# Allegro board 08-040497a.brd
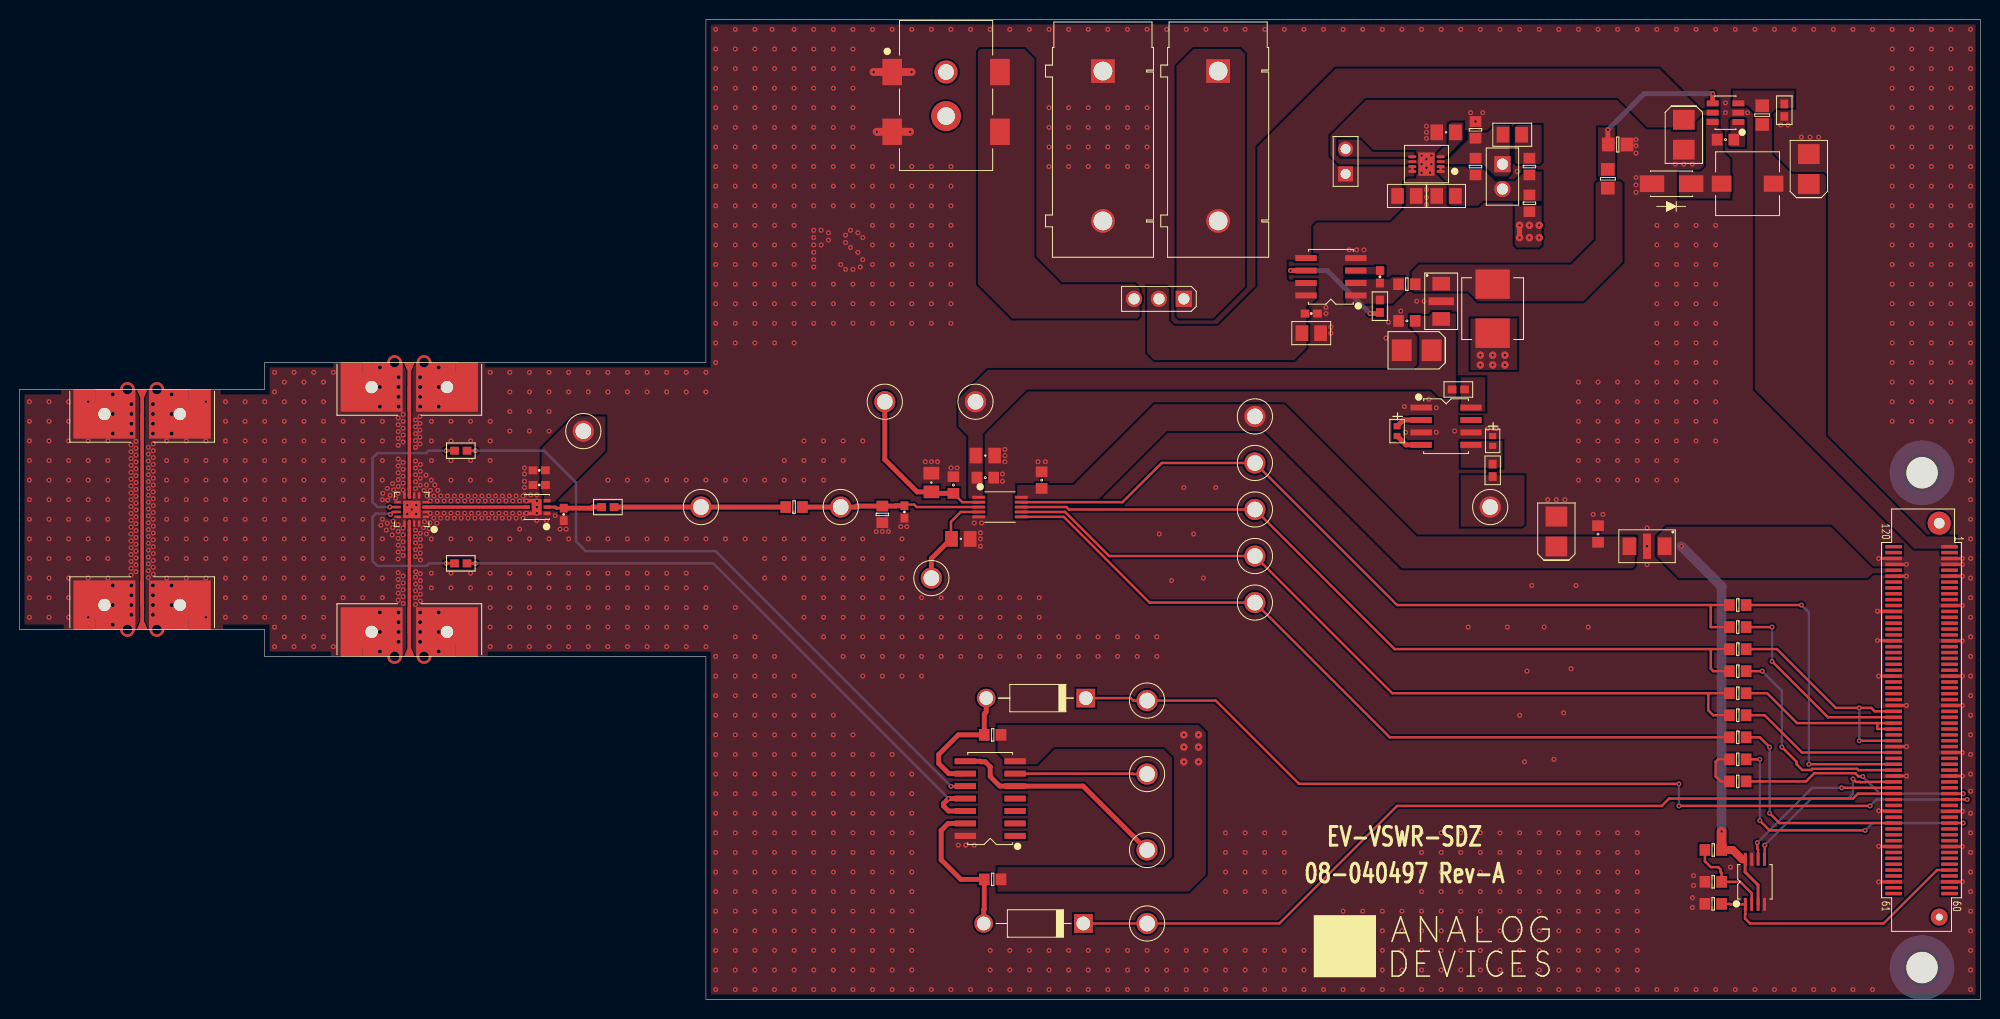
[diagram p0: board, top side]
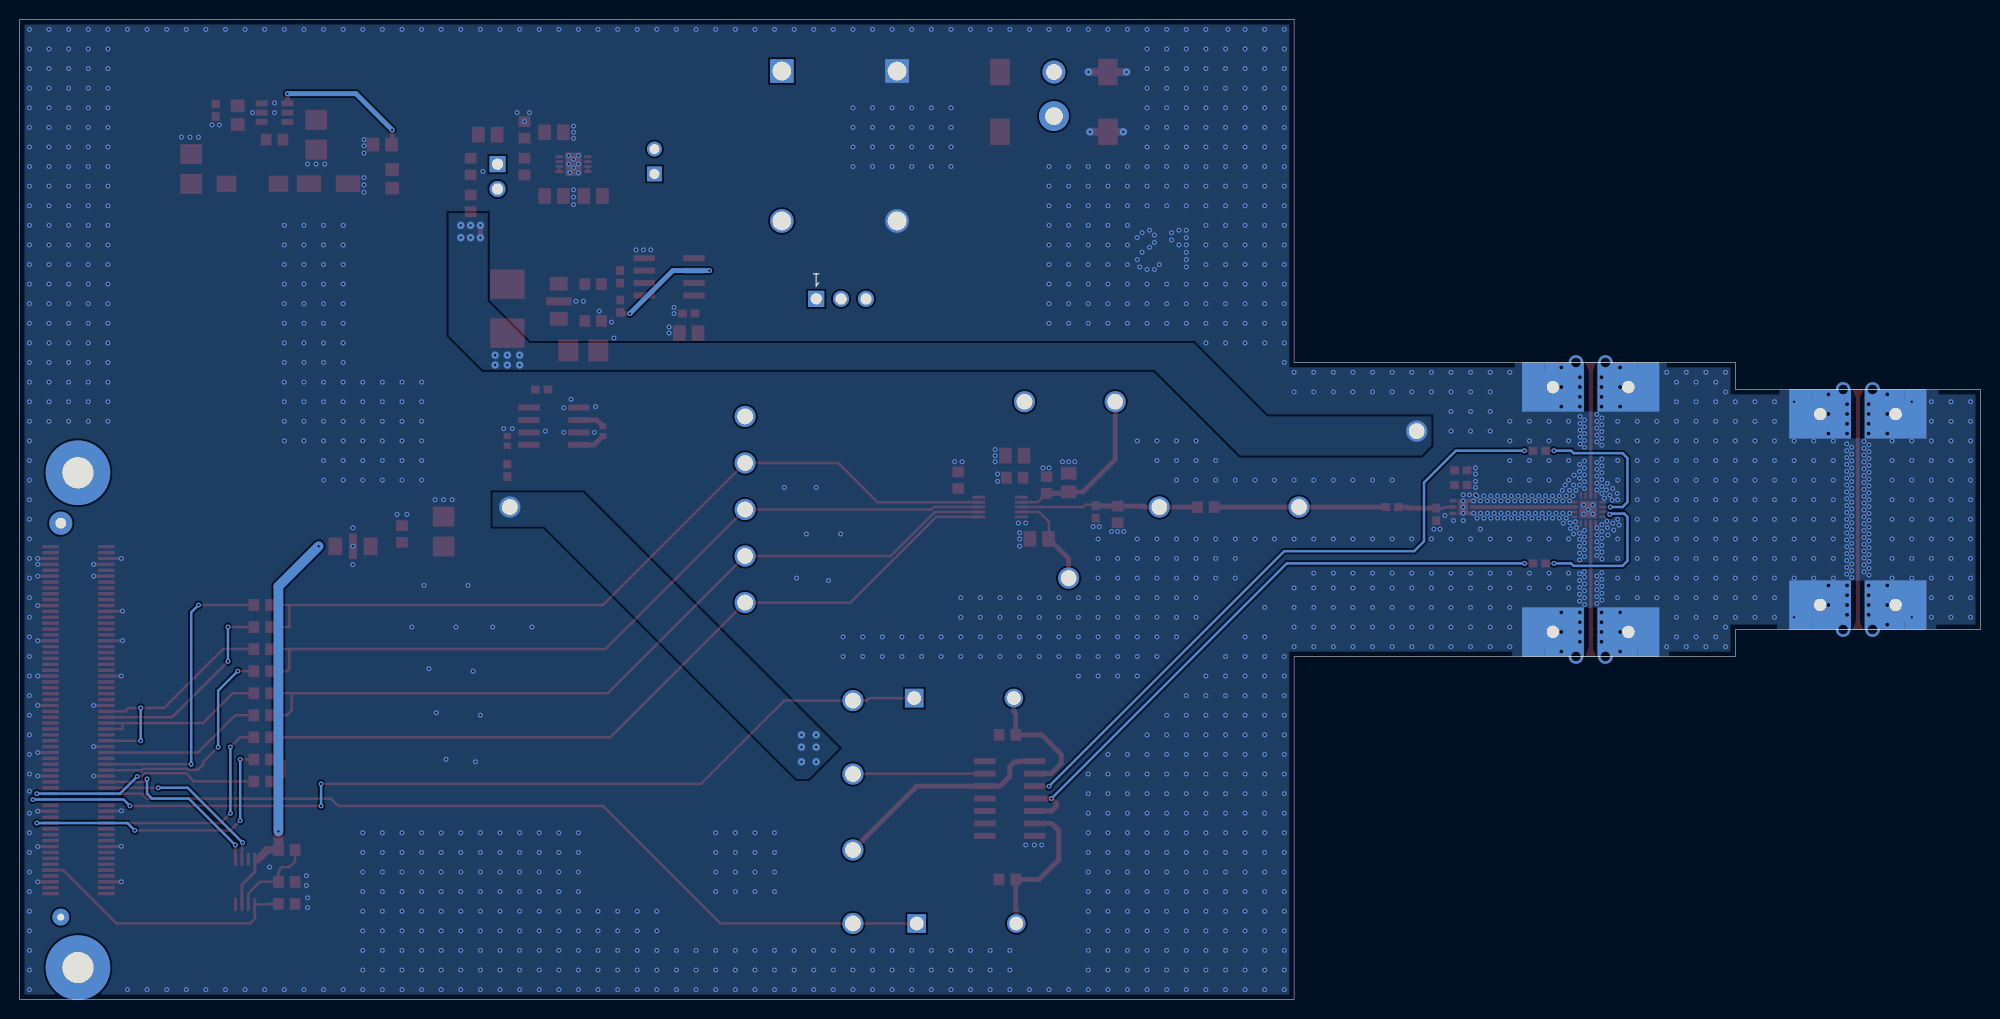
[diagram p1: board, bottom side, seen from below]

Outline 200 x 100 mm; copper layers: TOP, L2-GND, L3-GND, BOTTOM. Coordinates in mm from the lower left corner of the outline.
Outline path: 0,62.25 0,37.75 25,37.75 25,35 70,35 70,0 200,0 200,100 70,100 70,65 25,65 25,62.25 0,62.25

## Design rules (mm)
nets with their own width: min track width 0.3; nets AGND

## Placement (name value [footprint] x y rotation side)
A  WHT  [CNLOOPTP]  115 15.25 0 top
B  WHT  [CNLOOPTP]  115 23 0 top
C1  100pF  [C0402]  53 54 180 top
C2  0.1UF  [C0402]  53 52.5 180 top
C3  TBD0402  [C0402]  55.5 49.5 270 top
C9  1uF  [C0805]  98.5 55.5 0 top
C10  0.1uF  [C0603]  98.5 53.25 0 top
C11  0.1uF  [C0603]  95.25 52.5 90 top
C12  1uF  [C0805]  93 52.75 90 top
C14  1uF  [C0805]  96 47 0 top
C15  0.1uF  [C0603]  104.25 53 90 top
C17  0.01uF  [C0402]  131.75 70 0 top
C18  0.01UF  [C0402]  138.75 73.75 270 top
C19  0.1uF  [C0603]  141.5 69.25 180 top
C20  10uF  [C3528]  142.5 66.25 180 top
C21  10uF  [C3528]  169.75 88.25 270 top
C22  0.1uF  [C0603]  174 87.75 180 top
C23  10uF  [C3528]  182.5 84.75 90 top
C24  0.1uF  [C0603]  161 47.5 90 top
C25  10uF  [C3528]  156.75 47.75 90 top
C26  1UF  [C0805H53]  131.75 68 0 top
C29  1UF  [C0805H53]  152.25 88.25 0 top
C30  4.7UF  [C0805H53]  145.5 82 0 top
C31  1000pF  [C0805]  145.5 88.5 0 top
C32  4.7UF  [C0805H53]  141.5 82 180 top
C35  10uF  [CPL0402]  150.25 57 270 top
C36  10uF  [CPL0402]  140.5 58 270 top
C37  TBD0402  [C0402]  90.25 49.75 270 top
D1  B230A-13-F  [SMA-2]  168.5 83.25 180 top
D2  1N4733A  [DO41]  108.5 7.75 180 top
D3  1N4733A  [DO41]  108.75 30.75 180 top
GND  571-0100  [CNDELTRON-571]  110.5 94.75 270 top
GPIO1  WHT  [CNLOOPTP]  115 7.75 0 top
GPIO2  WHT  [CNLOOPTP]  115 30.5 0 top
J3  02K243-40M  [CNROS02K243-40M]  12.5 37.75 270 top
J4  FX8-120S-SV(21)  [CNHRSFX8-120S-SV_A]  194 28.5 270 top
J5  02K243-40M  [CNROS02K243-40M]  12.5 62.25 90 top
L1  6.8uH  [LSMSQ236H79_B]  176.25 83.25 0 top
L2  33uH  [L2525]  150.25 70.5 90 top
LC1  1000pF  [FLSML126W71H87]  145 71.25 270 top
LC2  1000pF  [FLSML126W71H87]  166 46.25 180 top
LK6  SAMTECTSW10608GS3PIN  [CNBERG1X3H205LD36]  118.75 71.5 180 top
LK21  M20-9990245  [CNHARWIN-M20-9990246]  151.25 85.25 270 top
LK22  69157-102  [CNBERG69157-102]  135.25 84.25 90 top
NOREF  -  []  261.5 -98 0 top
NOREF#2  -  []  40.54 48.23 0 top
NOREF#3  -  []  70 0 90 top
NOREF#4  -  []  39.11 52.78 0 top
NOREF#5  -  []  -153.6 -177.4 0 top
NOREF#6  -  []  200 0 90 top
NOREF#7  -  []  40.89 52.79 0 top
NOREF#8  -  []  0 62.25 0 top
NOREF#9  -  []  0 37.75 90 top
NOREF#10  -  []  -153.6 -177.4 0 top
NOREF#11  -  []  25 65 0 top
NOREF#12  -  []  70 65 90 top
NOREF#13  -  []  44.08 49.26 0 top
NOREF#14  -  []  -133.3 -28.65 0 top
NOREF#15  -  []  70 100 0 top
NOREF#16  -  []  25 62.25 90 top
NOREF#17  -  []  25 35 90 top
NOREF#18  -  []  38.12 33.5 0 top
NOREF#19  -  []  41.3 51.3 0 top
NOREF#20  -  []  -153.6 -177.4 0 top
NOREF#21  -  []  245.81 331.87 0 top
NOREF#22  -  []  129.5 140.25 0 top
NOREF#23  -  []  44.07 50.74 0 top
NOREF#24  -  []  132 2.25 180 bottom
R1  0  [R0402]  60 50.25 0 top
R12  330K  [R0402]  138.75 70.75 90 top
R13  3K  [R0805]  162 83.75 90 top
R14  1.5K  [R0805]  163 87.25 0 top
R15  53.6K  [R0805]  177.75 90.25 90 top
R16  10.2K  [R0402]  180 90.75 270 top
R17  TBD0603  [R0603]  175.25 33.5 180 top
R18  TBD0603  [R0603]  175.25 40.25 180 top
R19  TBD0603  [R0603]  175.25 29 180 top
R20  0  [R0603]  175.25 35.75 180 top
R21  0  [R0603]  175.25 31.25 180 top
R22  0  [R0603]  175.25 38 180 top
R23  0  [R0603]  175.25 24.5 0 top
R24  TBD0603  [R0603]  175.25 22.25 0 top
R25  TBD0603  [R0603]  175.25 26.75 180 top
R26  TBD0603  [R0603]  172.75 15.25 180 top
R27  100K  [R0603]  172.75 12 180 top
R28  100K  [R0603]  172.75 9.75 180 top
R30  10K  [R0603]  99.25 12.25 0 top
R31  200  [R0603]  79 50.25 0 top
R32  0  [R0603]  154 81.25 270 top
R33  3K  [R0603]  154 85 270 top
R34  120K  [R0603]  148.5 85 270 top
R35  39K  [R0603]  148.5 88.75 270 top
R36  10K  [R0603]  99.25 27 0 top
R37  0  [R0402]  146.75 62.25 180 top
R38  0  [R0402]  150.25 54 270 top
R39  0  [R0603]  141.5 73 0 top
R40  340  [R0603]  88 49.5 270 top
R41  100  [R0402]  45 44.5 180 top
R42  100  [R0402]  45 56 180 top
RF1  02K243-40M  [CNROS02K243-40M]  39.75 65 90 top
RF2  02K243-40M  [CNROS02K243-40M]  39.75 35 270 top
T1  WHT  [CNLOOPTP]  97.5 61 0 top
T2  WHT  [CNLOOPTP]  88.25 61 0 top
T3  WHT  [CNLOOPTP]  83.75 50.25 0 top
T4  WHT  [CNLOOPTP]  93 43 0 top
T6  WHT  [CNLOOPTP]  126 40.5 0 top
T7  WHT  [CNLOOPTP]  126 45.25 0 top
T8  WHT  [CNLOOPTP]  126 50 0 top
T9  WHT  [CNLOOPTP]  126 54.75 0 top
T10  WHT  [CNLOOPTP]  126 59.5 0 top
U1  ADL6010ACPZN  [UQFN6_2_05X2_05_PAD1_6X1_A]  52.75 50.25 90 top
U2  AD7091RBRMZ  [RM10]  100 50.25 270 top
U5  24LC32A-I/MS  [MSOP8]  177 12 0 top
U6  ADP3303ARZ-5  [SO8]  133.75 73.75 90 top
U7  ADP2301AUJZ  [TSOT23_6]  174 90.5 90 top
U8  ADM7170ACPZ  [DFN8_3X3_PAD2_38X1_64]  143.5 85.25 90 top
U9  74LV04AD  [SO14]  99 20.5 90 top
U10  -  [HMC547LP3E]  40 50 90 top
U11  ADM660ARZ  [SO8]  145.5 58.5 270 top
V_OUT  WHT  [CNLOOPTP]  69.5 50.25 0 top
VDET  RED  [CNLOOPTP]  57.5 58 0 top
VNEG  WHT  [CNLOOPTP]  150 50.25 0 top
VSUPPLY  KLDX-SMT2-0202-ATR  [CNKYCONKLDX-SMT2-0202]  94.5 92.25 270 top
VSUPPLY_ALT  571-0500  [CNDELTRON-571]  122.25 94.75 270 top

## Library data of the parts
A B GPIO1 GPIO2 T1-T4 T6-T10 V_OUT VNEG = CNTP1P: User Part Number: UPN; alternate symbols: (CNBANANA_ALT); part number: CNTP1P_TH-WHT,E000946,CNLOOPTP
C1 = CAP: Tolerance: 5; User Part Number: UPN; part number: CAP_SM-100PF,50V,5,E007896,C0402; tolerance: 5
C2 = CAP: Tolerance: 10; User Part Number: UPN; part number: CAP_SM-0.1UF,16V,10,E007200,C0402; tolerance: 10
C3 C37 = CAP: User Part Number: UPN; part number: CAP_SM-TBD0402,TBD0402,TBD0402,E000381,C0402
C9 C12 C14 = CAP: Tolerance: 10; User Part Number: UPN; part number: CAP_SM-1UF,100V,10,E014208,C0805; tolerance: 10
C10 C11 = CAP: Tolerance: 10; User Part Number: UPN; part number: CAP_SM-0.1UF,50V,10,E011865,C0603; tolerance: 10
C15 C19 C22 C24 = CAP: Tolerance: 10; User Part Number: UPN; part number: CAP_SM-0.1UF,50V,10,E015248,C0603; tolerance: 10
C17 = CAP: Tolerance: -0.25; User Part Number: UPN; part number: CAP_SM-0.01UF,50V,-0.25,E012614,C0402; tolerance: -0.25
C18 = CAP: Tolerance: 10; User Part Number: UPN; part number: CAP_SM-0.01UF,25V,10,E010983,C0402; tolerance: 10
C20 C21 C23 C25 = CAPP: User Part Number: UPN; Tolerance: 10; part number: CAPP_SM-10UF,20V,10,E011346,C3528; tolerance: 10
C26 C29 = CAP: Tolerance: 10; User Part Number: UPN; part number: CAP_SM-1UF,50V,10,E007202,C0805H53; tolerance: 10
C30 C32 = CAP: Tolerance: 10; User Part Number: UPN; part number: CAP_SM-4.7UF,25V,10,E006908,C0805H53; tolerance: 10
C31 = CAP: Tolerance: 5; User Part Number: UPN; part number: CAP_SM-1000PF,50V,5,E010100,C0805; tolerance: 5
C35 C36 = CAPP: User Part Number: UPN; Tolerance: 20; part number: CAPP_SM-10UF,6.3V,20,E022099,CPL0402; tolerance: 20
D1 = DIOSCHOTTKY: User Part Number: UPN; Tolerance: N/A; alternate symbols: (SOD882L_ALT); part number: DIOSCHOTTKY_SM-B230A-13-F,30V,N/A,E012952,SMA-2; tolerance: N/A
D2 D3 = DIOZNR: Tolerance: 5; User Part Number: UPN; part number: DIOZNR_TH-1N4733A,5.1V,5,E001229,DO41; tolerance: 5
GND = CN2P: User Part Number: UPN; part number: CN2P_TH-571-0100,E007691,CNDELTRON-571
J3 J5 RF1 RF2 = CNBNC3P: User Part Number: UPN; alternate symbols: (CNROS32K243-40ML5_ALT); part number: CNBNC3P_SM-02K243-40M,E010821,CNROS02K243-40M
J4 = CN120P_V4: User Part Number: UPN; part number: CN120P_V4_SM-FX8-120S-SV(21),E016993,CNHRSFX8-120S-SV_A
L1 = IND: Tolerance: 30; User Part Number: UPN; alternate symbols: (L0402-2,L0603_ALT,L1008L_ALT); part number: IND_SM-6.8UH,30,E021189,LSMSQ236H79_B; tolerance: 30
L2 = IND: Tolerance: 20; User Part Number: UPN; alternate symbols: (L0402-2,L0603_ALT,L1008L_ALT); part number: IND_SM-33UH,20,E002425,L2525; tolerance: 20
LC1 LC2 = FLTR3P_V3: User Part Number: UPN; part number: FLTR3P_V3_SM-1000PF,E019686,FLSML126W71H87
LK6 = CN3P: User Part Number: UPN; part number: CN3P_TH-SAMTECTSW10608GS3PIN,E000812,CNBERG1X3H205LD36
LK21 = CNJMPRSHRT: User Part Number: UPN; part number: CNJMPRSHRT_TH-M20-9990245,E019487,CNHARWIN-M20-9990246
LK22 = CNJMPRSHRT: User Part Number: UPN; part number: CNJMPRSHRT_TH-69157-102,E000942,CNBERG69157-102
R1 R37 R38 = RES: Tolerance: 5; User Part Number: UPN; part number: RES_SM-0,E003438,1/16W,5,R0402; tolerance: 5
R12 = RES: Tolerance: 5; User Part Number: UPN; part number: RES_SM-330K,E003461,1/16W,5,R0402; tolerance: 5
R13 = RES: Tolerance: 0.1; User Part Number: UPN; part number: RES_SM-3K,E013665,1/4W,0.1,R0805; tolerance: 0.1
R14 = RES: Tolerance: 0.1; User Part Number: UPN; part number: RES_SM-1.5K,E003822,1/10W,0.1,R0805; tolerance: 0.1
R15 = RES: Tolerance: 1; User Part Number: UPN; part number: RES_SM-53.6K,E003980,1/8W,1,R0805; tolerance: 1
R16 = RES: Tolerance: 1; User Part Number: UPN; part number: RES_SM-10.2K,E019451,1/16W,1,R0402; tolerance: 1
R17-R19 R24-R26 = RES: User Part Number: UPN; part number: RES_SM-TBD0603,E004050,TBD0603,TBD0603,R0603
R20-R23 R32 R39 = RES: Tolerance: 1; User Part Number: UPN; part number: RES_SM-0,E004207,1/16W,1,R0603; tolerance: 1
R27 R28 = RES: Tolerance: 1; User Part Number: UPN; part number: RES_SM-100K,E018430,1/16W,1,R0603; tolerance: 1
R30 R36 = RES: Tolerance: 0.1; User Part Number: UPN; part number: RES_SM-10K,E003965,1/10W,0.1,R0603; tolerance: 0.1
R31 = RES: Tolerance: 0.1; User Part Number: UPN; part number: RES_SM-200,E003955,1/10W,0.1,R0603; tolerance: 0.1
R33 = RES: Tolerance: 5; User Part Number: UPN; part number: RES_SM-3K,E003850,1/10W,5,R0603; tolerance: 5
R34 = RES: Tolerance: 1; User Part Number: UPN; part number: RES_SM-120K,E007774,0.1W,1,R0603; tolerance: 1
R35 = RES: Tolerance: 1; User Part Number: UPN; part number: RES_SM-39K,E004234,1/16W,1,R0603; tolerance: 1
R40 = RES: Tolerance: 1; User Part Number: UPN; part number: RES_SM-340,E012541,1/10W,1,R0603; tolerance: 1
R41 R42 = RES: Tolerance: 1; User Part Number: UPN; part number: RES_SM-100,E003760,1/16W,1,R0402; tolerance: 1
U1 = ADL6010: User Part Number: UPN; alternate symbols: (UQFN6_2_05X2_05_PAD1_6X1); part number: ADL6010_SM-ADL6010ACPZN,E019839,UQFN6_2_05X2_05_PAD1_6X1_A
U2 = AD7091R_V2: User Part Number: UPN; part number: AD7091R_V2_SM-AD7091RBRMZ,E015495,RM10
U5 = IC24FC256: User Part Number: UPN; part number: IC24FC256_SM-24LC32A-I/MS,E014160,MSOP8
U6 = ADP3303: User Part Number: UPN; part number: ADP3303_SM-ADP3303ARZ-5,E004966,SO8
U7 = ADP2301: User Part Number: UPN; part number: ADP2301_SM-ADP2301AUJZ,E007310,TSOT23_6
U8 = ADM7170: User Part Number: UPN; part number: ADM7170_SM-ADM7170ACPZ,E020662,DFN8_3X3_PAD2_38X1_64
U9 = 7404: User Part Number: UPN; part number: 7404_SM-74LV04AD,E002109,SO14
U10 = ICHMC547LP3E: User Part Number: UPN; part number: ICHMC547LP3E_SM-HMC547LP3E,E011702,HMC547LP3E
U11 = ADM660: User Part Number: UPN; part number: ADM660_TH-ADM660ARZ,E006022,SO8
VDET = CNTP1P: User Part Number: UPN; alternate symbols: (CNBANANA_ALT); part number: CNTP1P_TH-RED,E000947,CNLOOPTP
VSUPPLY = CN4P_V2: User Part Number: UPN; part number: CN4P_V2_SM-KLDX-SMT2-0202-ATR,E015303,CNKYCONKLDX-SMT2-0202
VSUPPLY_ALT = CN2P: User Part Number: UPN; part number: CN2P_TH-571-0500,E007692,CNDELTRON-571

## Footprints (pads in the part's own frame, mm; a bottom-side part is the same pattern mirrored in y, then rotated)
C0402
  rect 0.889x0.813 smd: 1(-0.635,0) 2(0.635,0)
C0603
  rect 1.092x1.194 smd: 1(-0.851,0) 2(0.851,0)
C0805
  rect 1.295x1.6 smd: 1(-0.953,0) 2(0.953,0)
C0805H53
  rect 1.295x1.6 smd: 1(-0.953,0) 2(0.953,0)
C3528
  rect 2.032x2.21 smd: N(1.524,0) P(-1.524,0)
CNBERG1X3H205LD36
  rect 1.651x1.651 hole 1.143: 1(0,0)
  round 1.651 hole 1.143: 2(2.54,0) 3(5.08,0)
CNBERG69157-102
  rect 1.524x1.524 hole 1.016: 1(0,0)
  round 1.524 hole 1.016: 2(2.54,0)
CNDELTRON-571
  rect 2.413x2.413 hole 1.905: 1(0,0)
  round 2.413 hole 1.905: 2(15.3,0)
CNHARWIN-M20-9990246
  rect 1.651x1.651 hole 1.143: 1(0,0)
  round 1.651 hole 1.143: 2(2.54,0)
CNHRSFX8-120S-SV_A
  round 3.302 hole 3.175 unplated: (-25.25,0.05) (25.25,0.05)
  round 2.362 hole 1.092 unplated: (-20.1,1.8)
  round 1.727 hole 0.711 unplated: (20.1,1.8)
  rect 0.356x1.702 smd: 1(-17.7,2.851) 2(-17.1,2.851) 3(-16.5,2.851) 4(-15.9,2.851) 5(-15.3,2.851) 6(-14.7,2.851) 7(-14.1,2.851) 8(-13.5,2.851) 9(-12.9,2.851) 10(-12.3,2.851) 11(-11.7,2.851) 12(-11.1,2.851) 13(-10.5,2.851) 14(-9.9,2.851) 15(-9.3,2.851) 16(-8.7,2.851) 17(-8.1,2.851) 18(-7.5,2.851) 19(-6.9,2.851) 20(-6.3,2.851) 21(-5.7,2.851) 22(-5.1,2.851) 23(-4.5,2.851) 24(-3.9,2.851) 25(-3.3,2.851) 26(-2.7,2.851) 27(-2.1,2.851) 28(-1.5,2.851) 29(-0.9,2.851) 30(-0.3,2.851) 31(0.3,2.851) 32(0.9,2.851) 33(1.5,2.851) 34(2.1,2.851) 35(2.7,2.851) 36(3.3,2.851) 37(3.9,2.851) 38(4.5,2.851) 39(5.1,2.851) 40(5.7,2.851) 41(6.3,2.851) 42(6.9,2.851) 43(7.5,2.851) 44(8.1,2.851) 45(8.7,2.851) 46(9.3,2.851) 47(9.9,2.851) 48(10.5,2.851) 49(11.1,2.851) 50(11.7,2.851) 51(12.3,2.851) 52(12.9,2.851) 53(13.5,2.851) 54(14.1,2.851) 55(14.7,2.851) 56(15.3,2.851) 57(15.9,2.851) 58(16.5,2.851) 59(17.1,2.851) 60(17.7,2.851) 61(17.7,-2.851) 62(17.1,-2.851) 63(16.5,-2.851) 64(15.9,-2.851) 65(15.3,-2.851) 66(14.7,-2.851) 67(14.1,-2.851) 68(13.5,-2.851) 69(12.9,-2.851) 70(12.3,-2.851) 71(11.7,-2.851) 72(11.1,-2.851) 73(10.5,-2.851) 74(9.9,-2.851) 75(9.3,-2.851) 76(8.7,-2.851) 77(8.1,-2.851) 78(7.5,-2.851) 79(6.9,-2.851) 80(6.3,-2.851) 81(5.7,-2.851) 82(5.1,-2.851) 83(4.5,-2.851) 84(3.9,-2.851) 85(3.3,-2.851) 86(2.7,-2.851) 87(2.1,-2.851) 88(1.5,-2.851) 89(0.9,-2.851) 90(0.3,-2.851) 91(-0.3,-2.851) 92(-0.9,-2.851) 93(-1.5,-2.851) 94(-2.1,-2.851) 95(-2.7,-2.851) 96(-3.3,-2.851) 97(-3.9,-2.851) 98(-4.5,-2.851) 99(-5.1,-2.851) 100(-5.7,-2.851) 101(-6.3,-2.851) 102(-6.9,-2.851) 103(-7.5,-2.851) 104(-8.1,-2.851) 105(-8.7,-2.851) 106(-9.3,-2.851) 107(-9.9,-2.851) 108(-10.5,-2.851) 109(-11.1,-2.851) 110(-11.7,-2.851) 111(-12.3,-2.851) 112(-12.9,-2.851) 113(-13.5,-2.851) 114(-14.1,-2.851) 115(-14.7,-2.851) 116(-15.3,-2.851) 117(-15.9,-2.851) 118(-16.5,-2.851) 119(-17.1,-2.851) 120(-17.7,-2.851)
CNKYCONKLDX-SMT2-0202
  round 2.362 hole 1.6 unplated: (-2.4,0)
  round 3.048 hole 1.803 unplated: (2.1,0)
  rect 2.692x2.007 smd: 1(-2.4,-5.497) 2(3.7,-5.497) 3(3.7,5.497) 4(-2.4,5.497)
CNLOOPTP
  round 2.159 hole 1.6: 1(0,0)
CNROS02K243-40M
  custom 0.275x0.275 smd: 1(-2.5,0)
  custom 1.251x1.251 hole 2.108: 2(-2.508,3.848) 3(-2.508,-3.848)
CPL0402
  rect 0.635x0.711 smd: N(0.5,0) P(-0.5,0)
DFN8_3X3_PAD2_38X1_64
  oval 0.305x0.838 smd: 1(-0.75,-1.45) 2(-0.25,-1.45) 3(0.25,-1.45) 4(0.75,-1.45) 5(0.75,1.45) 6(0.25,1.45) 7(-0.25,1.45) 8(-0.75,1.45)
  rect 2.388x1.651 smd: PAD(0,0)
DO41
  round 1.905 hole 1.397: A(10.16,0)
  rect 1.905x1.905 hole 1.397: C(0,0)
FLSML126W71H87
  rect 1.397x1.803 smd: 1(-1.799,0) 3(1.799,0)
  rect 0.813x2.591 smd: 2(0,0)
HMC547LP3E
  rect 0.254x0.66 smd: 1(-0.751,-1.435) 2(-0.25,-1.435) 3(0.25,-1.435) 4(0.751,-1.435) 9(0.751,1.435) 10(0.25,1.435) 11(-0.25,1.435) 12(-0.751,1.435)
  rect 0.66x0.254 smd: 5(1.435,-0.751) 6(1.435,-0.25) 7(1.435,0.25) 8(1.435,0.751) 13(-1.435,0.751) 14(-1.435,0.25) 15(-1.435,-0.25) 16(-1.435,-0.751)
  rect 1.778x1.778 smd: PAD(0,0)
L2525
  rect 2.997x3.505 smd: 1(-2.502,0) 2(2.502,0)
LSMSQ236H79_B
  rect 2.007x1.651 smd: 1(-2.65,0) 2(2.65,0)
MSOP8
  rect 0.305x1.321 smd: 1(-0.975,-2.3) 2(-0.325,-2.3) 3(0.325,-2.3) 4(0.975,-2.3) 5(0.975,2.3) 6(0.325,2.3) 7(-0.325,2.3) 8(-0.975,2.3)
R0402
  rect 0.889x0.813 smd: 1(-0.635,0) 2(0.635,0)
R0603
  rect 1.092x1.194 smd: 1(-0.851,0) 2(0.851,0)
R0805
  rect 1.295x1.397 smd: 1(-0.953,0) 2(0.953,0)
RM10
  rect 0.305x1.321 smd: 1(-1,-2.171) 2(-0.5,-2.171) 3(0,-2.171) 4(0.5,-2.171) 5(1,-2.171) 6(1,2.171) 7(0.5,2.171) 8(0,2.171) 9(-0.5,2.171) 10(-1,2.171)
SMA-2
  rect 2.489x1.702 smd: A(1.995,0) C(-1.995,0)
SO8
  rect 0.61x2.184 smd: 1(-1.905,-2.54) 2(-0.635,-2.54) 3(0.635,-2.54) 4(1.905,-2.54) 5(1.905,2.54) 6(0.635,2.54) 7(-0.635,2.54) 8(-1.905,2.54)
SO14
  rect 0.61x2.184 smd: 1(-3.81,-2.54) 2(-2.54,-2.54) 3(-1.27,-2.54) 4(0,-2.54) 5(1.27,-2.54) 6(2.54,-2.54) 7(3.81,-2.54) 8(3.81,2.54) 9(2.54,2.54) 10(1.27,2.54) 11(0,2.54) 12(-1.27,2.54) 13(-2.54,2.54) 14(-3.81,2.54)
TSOT23_6
  rect 0.61x1.219 smd: 1(-0.95,-1.31) 2(0,-1.31) 3(0.95,-1.31) 4(0.95,1.31) 5(0,1.31) 6(-0.95,1.31)
UQFN6_2_05X2_05_PAD1_6X1_A
  rect 0.356x0.711 smd: 1(-0.65,-1.05) 2(0,-1.05) 3(0.65,-1.05) 4(0.65,1.05) 5(0,1.05) 6(-0.65,1.05)
  rect 1.6x0.991 smd: PAD(0,0)

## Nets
AGND: C1.2(N2) C2.2(N2) C3.2(N2) C9.2(N2) C10.2(N2) C11.2(N2) C12.2(N2) C14.2(N2) C15.2(N2) C17.2(N2) C19.2(N2) C20.N(N2) C21.N(N2) C23.N(N2) C24.2(N2) C25.N(N2) C26.2(N2) C30.1(N1) C31.1(N1) C32.1(N1) C35.P(N1) C37.2(N2) D1.A(P) GND.1(N1) GND.2(N2) J3.2(SH1) J3.3(SH2) J4.3(GND1) J4.4(GND2) J4.6(GND3) J4.11(GND4) J4.17(GND5) J4.23(GND6) J4.28(GND7) J4.36(GND8) J4.40(GND9) J4.46(GND10) J4.52(GND11) J4.58(GND12) J4.63(GND13) J4.69(GND14) J4.75(GND15) J4.81(GND16) J4.86(GND17) J4.93(GND18) J4.98(GND19) J4.104(GND20) J4.109(GND21) J4.115(GND22) J4.117(GND23) J4.118(GND24) J5.2(SH1) J5.3(SH2) LC1.2(C) LC2.2(C) R14.2(N2) R16.2(N2) R27.2(N2) R28.2(N2) R35.1(N1) R40.2(N2) RF1.2(SH1) RF1.3(SH2) RF2.2(SH1) RF2.3(SH2) U1.1(GND1) U1.4(GND2) U1.6(GND3) U1.PAD U2.5(GND) U5.4(VSS) U5.7(WP) U6.4(GND) U7.2(GND) U8.6(GND) U8.PAD(EP) U9.14(VDD) U10.1(NC1) U10.2(GND1) U10.4(GND2) U10.5(NC2) U10.6(GND3) U10.8(GND4) U10.9(NC3) U10.12(NC4) U10.13(GND5) U10.15(GND6) U10.16(NC5) U10.PAD U11.1(FC) U11.3(GND) U11.6(LV) VSUPPLY.1(N1) VSUPPLY.2(N2)
AVDD: C9.1(N1) C10.1(N1) C19.1(N1) C20.P(N1) LC1.3(L2) R37.2(N2) T1.1(N1) U2.1(VDD)
A: A.1(N1) U9.5(IN) U9.8(OUT_N)
B: B.1(N1) U9.6(OUT_N)
CONVST: R23.1(N1) R24.1(N1)
CONVSTB: R25.2(N2) T6.1(N1) U2.6(CONVST_N)
CSB: R19.2(N2) R21.2(N2) T7.1(N1) U2.7(CS_N)
GPIO1: D2.C(N) GPIO1.1(N1) J4.78(GPIO1)
GPIO2: D3.C(N) GPIO2.1(N1) J4.44(GPIO2)
RF1: RF1.1(CNTR) U10.7(RF1)
RF2: RF2.1(CNTR) U10.14(RF2)
RF_TRUE_CAL: J3.1(CNTR) J5.1(CNTR)
RFIN: U1.5(RFIN) U10.3(RFC)
SCLK: R17.2(N2) R20.2(N2) T8.1(N1) U2.8(SCLK)
SDO: R18.2(N2) R22.2(N2) T9.1(N1) U2.9(SDO)
UNNAMED_3_AD7091RV2_I14_REFOUT: C11.1(N1) C12.1(N1) T2.1(N1) U2.2(REFOUT)
UNNAMED_3_AD7091RV2_I14_VIN: C37.1(N1) R31.2(N2) R40.1(N1) T3.1(N1) U2.3(VIN)
UNNAMED_3_CAP_I29_N1: C14.1(N1) T4.1(N1) U2.4(REGCAP)
UNNAMED_4_ADM660_I4_CAP: C36.N(N2) U11.4(CAP-)
UNNAMED_4_ADM660_I4_CAP_1: C36.P(N1) U11.2(CAP+)
UNNAMED_4_ADM660_I4_OUT: C35.N(N2) R38.1(N1) U11.5(OUT)
UNNAMED_4_ADM660_I4_V: R37.1(N1) U11.8(V+)
UNNAMED_4_ADM7170_I67_EN: LK22.2(S2) U8.5(EN)
UNNAMED_4_ADM7170_I67_SENSE: C29.1(N1) LK21.1(S1) R34.1(N1) R35.2(N2) U8.3(SENSE)
UNNAMED_4_ADM7170_I67_SS: C31.2(N2) U8.4(SS)
UNNAMED_4_ADM7170_I67_VOUT1: C30.2(N2) LK21.2(S2) R32.1(N1) R33.2(N2) R34.2(N2) U8.1(VOUT1) U8.2(VOUT2)
UNNAMED_4_ADP2301_I57_BST: C22.1(N1) U7.1(BST)
UNNAMED_4_ADP2301_I57_EN: R13.2(N2) R14.1(N1) U7.4(EN)
UNNAMED_4_ADP2301_I57_FB: R15.2(N2) R16.1(N1) U7.3(FB)
UNNAMED_4_ADP2301_I57_SW: C22.2(N2) D1.C(N) L1.1(N1) U7.6(SW)
UNNAMED_4_ADP3303_I47_ERRN: R12.1(N1) U6.6(ERR_N)
UNNAMED_4_ADP3303_I47_NR: C18.1(N1) U6.3(NR)
UNNAMED_4_ADP3303_I47_OUT: C18.2(N2) R12.2(N2) R39.1(N1) U6.1(OUT) U6.2(OUT1)
UNNAMED_4_CAP_I91_N2: C29.2(N2) R33.1(N1)
UNNAMED_4_CN2P_I42_N1: LK6.1(N1) VSUPPLY_ALT.1(N1) VSUPPLY_ALT.2(N2)
UNNAMED_4_CN4PV2_I45_N3: LK6.3(N3) VSUPPLY.3(N3) VSUPPLY.4(N4)
UNNAMED_5_CN120PV4_I55_EEPROMA0: J4.56(EEPROM_A0) R28.1(N1) U5.1(A0)
UNNAMED_5_CN120PV4_I55_GPIO0: J4.43(GPIO0) R24.2(N2)
UNNAMED_5_CN120PV4_I55_SCL0: J4.79(SCL_0) U5.6(SCL)
UNNAMED_5_CN120PV4_I55_SDA0: J4.80(SDA_0) U5.5(SDA)
UNNAMED_5_CN120PV4_I55_SPICLK: J4.82(SPI_CLK) R17.1(N1)
UNNAMED_5_CN120PV4_I55_SPIMISO: J4.83(SPI_MISO) R18.1(N1)
UNNAMED_5_CN120PV4_I55_SPISELA: J4.85(SPI_SEL_A) R19.1(N1)
UNNAMED_5_CN120PV4_I55_SPORTDR0: J4.91(SPORT_DR0) R22.1(N1)
UNNAMED_5_CN120PV4_I55_SPORTRFS: J4.89(SPORT_TFS) J4.90(SPORT_RFS) R21.1(N1)
UNNAMED_5_CN120PV4_I55_SPORTRSC: J4.87(SPORT_TSCLK) J4.92(SPORT_RSCLK) R20.1(N1)
UNNAMED_5_CN120PV4_I55_TMRA: J4.48(TMR_A) R23.2(N2)
UNNAMED_5_CN120PV4_I55_TMRB: J4.73(TMR_B) R25.1(N1)
UNNAMED_5_IC24FC256_I33_A1: R26.2(N2) R27.1(N1) U5.2(A1)
UNNAMED_8_7404_I38_IN: R41.1(N1) U9.11(IN) U9.12(OUT_N)
UNNAMED_8_7404_I38_OUTN: R42.1(N1) U9.10(OUT_N)
UNNAMED_8_7404_I39_IN: D2.A(P) R30.1(N1) U9.13(IN)
UNNAMED_8_7404_I65_IN: D3.A(P) R36.1(N1) U9.9(IN)
UNNAMED_8_ADL6010_I98_VOUT: C3.1(N1) R1.1(N1) U1.2(VOUT)
UNNAMED_8_ICHMC547LP3E_I42_A: R41.2(N2) U10.11(A)
UNNAMED_8_ICHMC547LP3E_I42_B: R42.2(N2) U10.10(B)
V_IN: C17.1(N1) C21.P(N1) C26.1(N1) C32.2(N2) LK6.2(N2) LK22.1(S1) U6.5(SD_N) U6.7(IN) U6.8(IN1) U7.5(VIN) U8.7(VIN2) U8.8(VIN1)
V_OUT: R1.2(N2) R31.1(N1) V_OUT.1(N1)
VDET: C1.1(N1) C2.1(N1) L2.1(N1) R32.2(N2) U1.3(VPOS) VDET.1(N1)
VDRIVE: C15.1(N1) C24.1(N1) C25.P(N1) LC2.3(L2) T10.1(N1) U2.10(VDRIVE)
VIO_CONNECTOR: J4.116(VIO(+3.3V)) LC2.1(L1) R26.1(N1) U5.3(A2) U5.8(VCC)
VNEG: R30.2(N2) R36.2(N2) R38.2(N2) U9.7(VSS) VNEG.1(N1)
VSDP: C23.P(N1) J4.1(VIN) L1.2(N2) R15.1(N1)
VSDP_EN: L2.2(N2) LC1.1(L1) R13.1(N1) R39.2(N2)

Pads without a net: J4 2 5 7 8 9 10 12 13 14 15 16 18 19 20 21 22 24 25 26 27 29 30 31 32 33 34 35 37 38 39 41 42 45 47 49 50 51 53 54 55 57 59 60 61 62 64 65 66 67 68 70 71 72 74 76 77 84 88 94 95 96 97 99 100 101 102 103 105 106 107 108 110 111 112 113 114 119 120; U9 1 2 3 4; U11 7

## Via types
v1: diameter 0.508, hole 0.254, TOP to BOTTOM, 1742 vias
v2: diameter 0.762, hole 0.254, TOP to BOTTOM, 22 vias
v3: diameter 0.66, hole 0.406, TOP to BOTTOM, 55 vias
v4: diameter 1.499, hole 0.991, TOP to BOTTOM, 8 vias

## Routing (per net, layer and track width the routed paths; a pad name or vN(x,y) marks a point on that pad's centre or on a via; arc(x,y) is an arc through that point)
AGND: length 40.4
  TOP w0.3: J4.115 v1(192.45,43.2) ; J4.104 v1(189.5,36.62) ; J4.109 v1(189.5,39.62) ; J4.98 v1(189.62,33) ; J4.81 v1(192.45,22.8) ; J4.46 v1(198.16,19.2) ; J4.28 v1(198.16,30) ; J4.63 v1(189.62,12) ; J4.69 v1(189.62,15.62) ; J4.117 v1(192.45,44.4) ; J4.3 v1(198.16,45) ; J4.6 v1(198.16,43.2) ; J4.4 v1(198.16,44.4) ; J4.86 v1(192.45,25.8) ; J4.11 v1(198.16,40.2) ; J4.52 v1(198.16,15.6) ; J4.58 v1(198.16,12) ; J4.93 v1(192.45,30) ; J4.36 v1(198.16,25.2) ; J4.23 v1(198.16,33) ; J4.118 v1(189.62,45) ; J4.40 v1(198.16,22.8) ; J4.75 v1(189.62,19.25) ; J4.17 v1(198.16,36.6)
  TOP w0.8: v2(87.42,88.55) VSUPPLY.2 v2(90.83,88.55) ; v2(87.1,94.65) VSUPPLY.1 v2(90.97,94.65)
  vias: v1(1,61) v1(1,59) v1(1,57) v1(1,55) v1(1,53) v1(1,51) v1(1,49) v1(1,47) v1(1,45) v1(1,43) v1(1,41) v1(1,39) v1(3,61) v1(3,59) v1(3,57) v1(3,55) v1(3,53) v1(3,51) v1(3,49) v1(3,47) v1(3,45) v1(3,43) v1(3,41) v1(3,39) v1(5,61) v1(5,59) v1(5,57) v1(5,55) v1(5,53) v1(5,51) v1(5,49) v1(5,47) v1(5,45) v1(5,43) v1(5,41) v1(5,39) v1(7,61) v1(7,57) v1(7,55) v1(7,53) v1(7,51) v1(7,49) v1(7,47) v1(7,45) v1(7,43) v1(7,39) v1(9,57) v1(9,55) v1(9,53) v1(9,51) v1(9,49) v1(9,47) v1(9,45) v1(9,43) v1(11.37,56.6) v1(11.37,55.9) v1(11.37,55.2) v1(11.37,54.5) v1(11.37,53.8) v1(11.37,53.1) v1(11.37,52.4) v1(11.37,51.7) v1(11.37,51) v1(11.37,50.3) v1(11.37,49.6) v1(11.37,48.9) v1(11.37,48.2) v1(11.37,47.5) v1(11.37,46.8) v1(11.37,46.1) v1(11.37,45.4) v1(11.37,44.7) v1(11.37,44) v1(11.37,43.3) v1(11.87,56.95) v1(11.87,56.25) v1(11.87,55.55) v1(11.87,54.85) v1(11.87,54.15) v1(11.87,53.45) v1(11.87,52.75) v1(11.87,52.05) v1(11.87,51.35) v1(11.87,50.65) v1(11.87,49.95) v1(11.87,49.25) v1(11.87,48.55) v1(11.87,47.85) v1(11.87,47.15) v1(11.87,46.45) v1(11.87,45.75) v1(11.87,45.05) v1(11.87,44.35) v1(11.87,43.65) v1(13.13,56.35) v1(13.13,55.65) v1(13.13,54.95) v1(13.13,54.25) v1(13.13,53.55) v1(13.13,52.85) v1(13.13,52.15) v1(13.13,51.45) v1(13.13,50.75) v1(13.13,50.05) v1(13.13,49.35) v1(13.13,48.65) v1(13.13,47.95) v1(13.13,47.25) v1(13.13,46.55) v1(13.13,45.85) v1(13.13,45.15) v1(13.13,44.45) v1(13.13,43.75) v1(13.13,43.05) v1(13.63,56.7) v1(13.63,56) v1(13.63,55.3) v1(13.63,54.6) v1(13.63,53.9) v1(13.63,53.2) v1(13.63,52.5) v1(13.63,51.8) v1(13.63,51.1) v1(13.63,50.4) v1(13.63,49.7) v1(13.63,49) v1(13.63,48.3) v1(13.63,47.6) v1(13.63,46.9) v1(13.63,46.2) v1(13.63,45.5) v1(13.63,44.8) v1(13.63,44.1) v1(13.63,43.4) v1(15,57) v1(15,55) v1(15,53) v1(15,51) v1(15,49) v1(15,47) v1(15,45) v1(15,43) v1(17,57) v1(17,55) v1(17,53) v1(17,51) v1(17,49) v1(17,47) v1(17,45) v1(17,43) v1(19,61) v1(19,57) v1(19,55) v1(19,53) v1(19,51) v1(19,49) v1(19,47) v1(19,45) v1(19,43) v1(19,39) v1(21,61) v1(21,59) v1(21,57) v1(21,55) v1(21,53) v1(21,51) v1(21,49) v1(21,47) v1(21,45) v1(21,43) v1(21,41) v1(21,39) v1(23,61) v1(23,59) v1(23,57) v1(23,55) v1(23,53) v1(23,51) v1(23,49) v1(23,47) v1(23,45) v1(23,43) v1(23,41) v1(23,39) v1(25,61) v1(25,59) v1(25,57) v1(25,55) v1(25,53) v1(25,51) v1(25,49) v1(25,47) v1(25,45) v1(25,43) v1(25,41) v1(25,39) v1(26,64) v1(26,62) v1(26,38) v1(26,36) v1(27,63) v1(27,61) v1(27,59) v1(27,57) v1(27,55) v1(27,53) v1(27,51) v1(27,49) v1(27,47) v1(27,45) v1(27,43) v1(27,41) v1(27,39) v1(27,37) v1(28,64) v1(28,36) v1(29,63) v1(29,61) v1(29,59) v1(29,57) v1(29,55) v1(29,53) v1(29,51) v1(29,49) v1(29,47) v1(29,45) v1(29,43) v1(29,41) v1(29,39) v1(29,37) v1(30,64) v1(30,36) v1(31,63) v1(31,61) v1(31,59) v1(31,57) v1(31,55) v1(31,53) v1(31,51) v1(31,49) v1(31,47) v1(31,45) v1(31,43) v1(31,41) v1(31,39) v1(31,37) v1(32,64) v1(32,36) v1(33,59) v1(33,57) v1(33,55) v1(33,53) v1(33,51) v1(33,49) v1(33,47) v1(33,45) v1(33,43) v1(33,41) v1(35,59) v1(35,57) v1(35,55) v1(35,53) v1(35,51) v1(35,49) v1(35,47) v1(35,45) v1(35,43) v1(35,41) v1(36.85,48.4) v1(37,59) v1(37,57) v1(37,55) v1(37,53) v1(37,51) v1(37,49) v1(37,47) v1(37,45) v1(37,43) v1(37,41) v1(37.05,51.65) v1(37.4,47.9) v1(37.5,52.15) v1(37.5,48.6) v1(37.55,50.95) v1(37.8,51.45) v1(38,47.4) v1(38.05,52.65) v1(38.1,48.8) v1(38.05,48.15) v1(38.15,52) v1(38.35,51.15) v1(38.62,61.45) v1(38.62,59.35) v1(38.62,58.65) v1(38.62,57.95) v1(38.62,57.25) v1(38.62,56.55) v1(38.62,55.15) v1(38.62,54.45) v1(38.62,53.75) v1(38.62,53.05) v1(38.62,52.35) v1(38.62,51.65) v1(38.62,48.46) v1(38.62,47.76) v1(38.62,47.06) v1(38.62,46.36) v1(38.62,45.66) v1(38.6,44.95) v1(38.62,43.56) v1(38.62,42.86) v1(38.62,42.16) v1(38.62,41.46) v1(38.62,40.76) v1(39.12,59.7) v1(39.12,59) v1(39.12,58.3) v1(39.12,57.6) v1(39.12,56.9) v1(39.12,54.8) v1(39.12,54.1) v1(39.12,53.4) v1(39.12,52.7) v1(39.12,52) v1(39.12,48.11) v1(39.12,47.41) v1(39.12,46.71) v1(39.12,46.01) v1(39.12,45.31) v1(39.12,43.21) v1(39.12,42.51) v1(39.12,41.81) v1(39.12,41.11) v1(39.12,40.41) v1(39.54,50.46) v1(39.54,49.54) v1(40,50) v1(40.38,59.14) v1(40.38,58.44) v1(40.38,57.74) v1(40.38,57.04) v1(40.38,56.34) v1(40.38,54.94) v1(40.38,54.24) v1(40.38,53.54) v1(40.38,52.84) v1(40.38,52.14) v1(40.38,47.87) v1(40.38,47.22) v1(40.38,46.6) v1(40.38,45.9) v1(40.38,45.2) v1(40.4,43.65) v1(40.38,43.1) v1(40.38,42.4) v1(40.38,41.7) v1(40.38,41) v1(40.38,40.3) v1(40.46,50.46) v1(40.46,49.54) v1(40.83,59.49) v1(40.83,58.79) v1(40.83,58.09) v1(40.83,57.39) v1(40.83,56.69) v1(40.88,62.59) v1(40.88,60.49) v1(40.88,54.59) v1(40.88,53.89) v1(40.88,53.19) v1(40.88,52.49) v1(40.88,47.58) v1(40.88,46.95) v1(40.88,46.25) v1(40.88,45.55) v1(40.88,44.85) v1(40.88,43.45) v1(40.88,42.75) v1(40.88,42.05) v1(40.88,41.35) v1(40.88,40.65) v1(41.25,51.95) v1(41.2,48.15) v1(41.3,48.75) v1(41.45,53.5) v1(41.5,52.5) v1(41.5,47.5) v1(41.55,51.38) v1(41.85,48.65) v1(41.8,48.05) v1(41.9,51.95) v1(41.9,50.88) v1(41.89,49.62) v1(42,59) v1(42,57) v1(42,55) v1(42,53) v1(42,47) v1(42,43.5) v1(42,42) v1(42.25,51.38) v1(42.24,49.12) v1(42.35,52.5) v1(42.6,50.88) v1(42.59,49.62) v1(42.55,48.6) v1(42.65,51.95) v1(42.95,51.38) v1(42.94,49.12) v1(43.3,50.88) v1(43.29,49.62) v1(43.64,49.12) v1(43.65,51.38) v1(44,59) v1(44,57) v1(44,55) v1(44,53) v1(44,50.88) v1(43.99,49.62) v1(44,47) v1(44,43.5) v1(44,42) v1(44.35,51.38) v1(44.34,49.12) v1(44.7,50.88) v1(44.69,49.62) v1(45.04,49.12) v1(45.05,51.38) v1(45.4,50.88) v1(45.39,49.62) v1(45.74,49.12) v1(45.75,51.38) v1(46,59) v1(46,57) v1(46,55) v1(46,53) v1(46,47) v1(46,43.5) v1(46,42) v1(46.1,50.88) v1(46.09,49.62) v1(46.45,51.38) v1(46.44,49.12) v1(46.8,50.88) v1(46.79,49.62) v1(47.14,49.12) v1(47.15,51.38) v1(47.5,50.88) v1(47.49,49.62) v1(47.85,51.38) v1(47.84,49.12) v1(48,64) v1(48,59) v1(48,57) v1(48,55) v1(48,53) v1(48,47) v1(48,43.5) v1(48,42) v1(48,40) v1(48,38) v1(48,36) v1(48.2,50.88) v1(48.19,49.62) v1(48.54,49.12) v1(48.55,51.38) v1(48.9,50.88) v1(48.89,49.62) v1(49.25,51.38) v1(49.24,49.12) v1(49.6,50.88) v1(49.59,49.62) v1(49.95,51.38) v1(49.94,49.12) v1(50,64) v1(50,62) v1(50,60) v1(50,58) v1(50,47) v1(50,43.5) v1(50,42) v1(50,40) v1(50,38) v1(50,36) v1(50.3,50.88) v1(50.29,49.62) v1(50.64,49.12) v1(50.65,51.38) v1(51,50.88) v1(50.99,49.62) v1(51,48) v1(51.35,51.38) v1(51.34,49.12) v1(51.5,54.25) v1(51.5,53.62) v1(51.5,52.88) v1(51.5,52.25) v1(51.5,51.5) v1(51.7,50.88) v1(51.69,49.62) v1(52,64) v1(52,62) v1(52,60) v1(52,58) v1(52,47) v1(52,43.5) v1(52,42) v1(52,40) v1(52,38) v1(52,36) v1(52.12,51.5) v1(52.75,51.5) v1(52.75,50.88) v1(52.75,50.25) v1(52.75,49.62) v1(52.75,48.88) v1(53.75,48.88) v1(54,64) v1(54,62) v1(54,60) v1(54,58) v1(54,47) v1(54,43.5) v1(54,42) v1(54,40) v1(54,38) v1(54,36) v1(54.62,49.38) v1(55.12,48) v1(55.75,48) v1(56,64) v1(56,62) v1(56,47) v1(56,43.5) v1(56,42) v1(56,40) v1(56,38) v1(56,36) v1(58,64) v1(58,62) v1(58,47) v1(58,43.5) v1(58,42) v1(58,40) v1(58,38) v1(58,36) v1(60,64) v1(60,62) v1(60,53) v1(60,47) v1(60,43.5) v1(60,42) v1(60,40) v1(60,38) v1(60,36) v1(62,64) v1(62,62) v1(62,53) v1(62,47) v1(62,43.5) v1(62,42) v1(62,40) v1(62,38) v1(62,36) v1(64,64) v1(64,62) v1(64,53) v1(64,47) v1(64,43.5) v1(64,42) v1(64,40) v1(64,38) v1(64,36) v1(66,64) v1(66,62) v1(66,53) v1(66,47) v1(66,43.5) v1(66,42) v1(66,40) v1(66,38) v1(66,36) v1(68,64) v1(68,62) v1(68,53) v1(68,47) v1(68,43.5) v1(68,42) v1(68,40) v1(68,38) v1(68,36) v1(70,64) v1(70,62) v1(70,53) v1(70,47) v1(70,42) v1(70,40) v1(70,38) v1(70,36) v1(71,99) v1(71,97) v1(71,95) v1(71,93) v1(71,91) v1(71,89) v1(71,87) v1(71,85) v1(71,83) v1(71,81) v1(71,79) v1(71,77) v1(71,75) v1(71,73) v1(71,71) v1(71,69) v1(71,67) v1(71,65) v1(71,35) v1(71,33) v1(71,31) v1(71,29) v1(71,27) v1(71,25) v1(71,23) v1(71,21) v1(71,19) v1(71,17) v1(71,15) v1(71,13) v1(71,11) v1(71,9) v1(71,7) v1(71,5) v1(71,3) v1(71,1) v1(72,53) v1(72,47) v1(73,99) v1(73,97) v1(73,95) v1(73,93) v1(73,91) v1(73,89) v1(73,87) v1(73,85) v1(73,83) v1(73,81) v1(73,79) v1(73,77) v1(73,75) v1(73,73) v1(73,71) v1(73,69) v1(73,67) v1(73,40) v1(73,37) v1(73,35) v1(73,33) v1(73,31) v1(73,29) v1(73,27) v1(73,25) v1(73,23) v1(73,21) v1(73,19) v1(73,17) v1(73,15) v1(73,13) v1(73,11) v1(73,9) v1(73,7) v1(73,5) v1(73,3) v1(73,1) v1(74,53) v1(74,47) v1(75,99) v1(75,97) v1(75,95) v1(75,93) v1(75,91) v1(75,89) v1(75,87) v1(75,85) v1(75,83) v1(75,81) v1(75,79) v1(75,77) v1(75,75) v1(75,73) v1(75,71) v1(75,69) v1(75,67) v1(75,37) v1(75,35) v1(75,33) v1(75,31) v1(75,29) v1(75,27) v1(75,25) v1(75,23) v1(75,21) v1(75,19) v1(75,17) v1(75,15) v1(75,13) v1(75,11) v1(75,9) v1(75,7) v1(75,5) v1(75,3) v1(75,1) v1(76,53) v1(76,47) v1(76,45) v1(76,43) v1(76.75,99) v1(77,97) v1(77,95) v1(77,93) v1(77,91) v1(77,89) v1(77,87) v1(77,85) v1(77,83) v1(77,81) v1(77,79) v1(77,77) v1(77,75) v1(77,73) v1(77,71) v1(77,69) v1(77,67) v1(77,35) v1(77,33) v1(77,31) v1(77,29) v1(77,27) v1(77,25) v1(77,23) v1(77,21) v1(77,19) v1(77,17) v1(77,15) v1(77,13) v1(77,11) v1(77,9) v1(77,7) v1(77,5) v1(77,3) v1(77,1) v1(78,55) v1(78,53) v1(78,47) v1(78,45) v1(78,43) v1(79,99) v1(79,97) v1(79,95) v1(79,93) v1(79,91) v1(79,89) v1(79,87) v1(79,85) v1(79,83) v1(79,81) v1(79,79) v1(79,77) v1(79,75) v1(79,73) v1(79,71) v1(79,69) v1(79,67) v1(79,33) v1(79,31) v1(79,29) v1(79,27) v1(79,25) v1(79,23) v1(79,21) v1(79,19) v1(79,17) v1(79,15) v1(79,13) v1(79,11) v1(79,9) v1(79,7) v1(79,5) v1(79,3) v1(79,1) v1(80,57) v1(80,55) v1(80,53) v1(80,47) v1(80,45) v1(80,43) v1(80,41) v1(80,39) v1(81,99) v1(81,97) v1(81,95) v1(81,93) v1(81,91) v1(81,89) v1(81,87) v1(81,85) v1(81,83) v1(81,81) v1(81,78.5) v1(81,77.75) v1(81,77) v1(81,76.25) v1(81,75.5) v1(81,74.75) v1(81,73) v1(81,71) v1(81,69) v1(81,31) v1(81,29) v1(81,27) v1(81,25) v1(81,23) v1(81,21) v1(81,19) v1(81,17) v1(81,15) v1(81,13) v1(81,11) v1(81,9) v1(81,7) v1(81,5) v1(81,3) v1(81,1) v1(81.75,78.5) v1(81.75,77) v1(82,57) v1(82,55) v1(82,53) v1(82,47) v1(82,45) v1(82,43) v1(82,41) v1(82,39) v1(82,37) v1(82.5,78.25) v1(82.5,77.5) v1(83,99) v1(83,97) v1(83,95) v1(83,93) v1(83,91) v1(83,89) v1(83,87) v1(83,85) v1(83,83) v1(83,81) v1(83,73) v1(83,71) v1(83,69) v1(83,29) v1(83,27) v1(83,25) v1(83,23) v1(83,21) v1(83,19) v1(83,17) v1(83,15) v1(83,13) v1(83,11) v1(83,9) v1(83,7) v1(83,5) v1(83,3) v1(83,1) v1(83.75,75) v1(84,57) v1(84,55) v1(84,47) v1(84,45) v1(84,43) v1(84,41) v1(84,39) v1(84,37) v1(84,35) v1(84.25,78) v1(84.25,77.25) v1(84.25,74.5) v1(84.75,78.5) v1(84.75,76.75) v1(85,99) v1(85,97) v1(85,95) v1(85,93) v1(85,91) v1(85,89) v1(85,87) v1(85,85) v1(85,83) v1(85,81) v1(85,74.5) v1(85,73) v1(85,71) v1(85,69) v1(85,27) v1(85,25) v1(85,23) v1(85,21) v1(85,19) v1(85,17) v1(85,15) v1(85,13) v1(85,11) v1(85,9) v1(85,7) v1(85,5) v1(85,3) v1(85,1) v1(85.5,78.25) v1(85.5,76.25) v1(85.75,74.75) v1(86,77.75) v1(86,75.5) v1(86,57) v1(86,47) v1(86,45) v1(86,43) v1(86,41) v1(86,39) v1(86,37) v1(86,35) v1(86,33) v1(87,99) v1(87,85) v1(87,83) v1(87,81) v1(87,79) v1(87,77) v1(87,75) v1(87,73) v1(87,71) v1(87,69) v1(87,25) v1(87,23) v1(87,21) v1(87,19) v1(87,17) v1(87,15) v1(87,13) v1(87,11) v1(87,9) v1(87,7) v1(87,5) v1(87,3) v1(87,1) v1(87.38,47.75) v1(88,47.75) v1(88,45) v1(88,43) v1(88,41) v1(88,39) v1(88,37) v1(88,35) v1(88,33) v1(88.62,47.75) v1(89,99) v1(89,85) v1(89,83) v1(89,81) v1(89,79) v1(89,77) v1(89,75) v1(89,73) v1(89,71) v1(89,69) v1(89,25) v1(89,23) v1(89,21) v1(89,19) v1(89,17) v1(89,15) v1(89,13) v1(89,11) v1(89,9) v1(89,7) v1(89,5) v1(89,3) v1(89,1) v1(89.88,48.25) v1(90,47) v1(90,45) v1(90,43) v1(90,41) v1(90,39) v1(90,37) v1(90,35) v1(90,33) v1(90.5,48.25) v1(91,99) v1(91,85) v1(91,83) v1(91,81) v1(91,79) v1(91,77) v1(91,75) v1(91,73) v1(91,71) v1(91,69) v1(91,23) v1(91,21) v1(91,19) v1(91,17) v1(91,15) v1(91,13) v1(91,11) v1(91,9) v1(91,7) v1(91,5) v1(91,3) v1(91,1) v1(92,41) v1(92,39) v1(92,37) v1(92,35) v1(92,33) v1(92.38,54.88) v1(93,99) v1(93,85) v1(93,83) v1(93,81) v1(93,79) v1(93,77) v1(93,75) v1(93,73) v1(93,71) v1(93,69) v1(93,54.88) v1(93,1) v1(93.62,54.88) v1(94,41) v1(94,39) v1(94,37) v1(94,35) v1(95,99) v1(95,85) v1(95,83) v1(95,81) v1(95,79) v1(95,77) v1(95,75) v1(95,73) v1(95,71) v1(95,69) v1(95,54.25) v1(95,1) v1(95.62,54.25) v1(95.75,15.75) v1(96,41) v1(96,39) v1(96,37) v1(96,35) v1(96.5,15.75) v1(97,99) v1(97,1) v1(97.38,48.62) v1(97.38,15.75) v1(98,47.62) v1(98,47) v1(98,46.25) v1(98,41) v1(98,39) v1(98,37) v1(98,35) v1(98.12,48.62) v1(99,99) v1(99,5) v1(99,3) v1(99,1) v1(100,41) v1(100,39) v1(100,37) v1(100,35) v1(100.25,53.62) v1(100.25,52.88) v1(100.5,56.12) v1(100.5,55.5) v1(100.5,54.88) v1(101,99) v1(101,5) v1(101,3) v1(101,1) v1(102,41) v1(102,39) v1(102,37) v1(102,35) v1(103,99) v1(103,5) v1(103,3) v1(103,1) v1(103.88,54.88) v1(104,41) v1(104,39) v1(104,37) v1(104,35) v1(104.62,54.88) v1(105,99) v1(105,91) v1(105,89) v1(105,87) v1(105,85) v1(105,5) v1(105,3) v1(105,1) v1(106,37) v1(106,35) v1(107,99) v1(107,91) v1(107,89) v1(107,87) v1(107,85) v1(107,5) v1(107,3) v1(107,1) v1(108,37) v1(108,35) v1(109,99) v1(109,91) v1(109,89) v1(109,87) v1(109,85) v1(109,5) v1(109,3) v1(109,1) v1(110,37) v1(110,35) v1(111,99) v1(111,91) v1(111,89) v1(111,87) v1(111,85) v1(111,5) v1(111,3) v1(111,1) v1(112,37) v1(112,35) v1(113,99) v1(113,91) v1(113,89) v1(113,87) v1(113,85) v1(113,5) v1(113,3) v1(113,1) v1(114,37) v1(114,35) v1(115,99) v1(115,91) v1(115,89) v1(115,87) v1(115,85) v1(115,5) v1(115,3) v1(115,1) v1(116,37) v1(116,35) v1(116.25,47.5) v1(117,99) v1(117,5) v1(117,3) v1(117,1) v1(117.5,42.75) v1(118.75,52.25) v1(119,99) v1(119,5) v1(119,3) v1(119,1) v1(119.75,47.5) v1(120.75,43) v1(121,99) v1(121,5) v1(121,3) v1(121,1) v1(122,52.25) v1(123,99) v1(123,17) v1(123,15) v1(123,13) v1(123,11) v1(123,5) v1(123,3) v1(123,1) v1(125,99) v1(125,17) v1(125,15) v1(125,13) v1(125,11) v1(125,5) v1(125,3) v1(125,1) v1(127,99) v1(127,17) v1(127,15) v1(127,13) v1(127,11) v1(127,5) v1(127,3) v1(127,1) v1(129,99) v1(129,17) v1(129,15) v1(129,13) v1(129,11) v1(129,5) v1(129,3) v1(129,1) v1(131,99) v1(131,5) v1(131,3) v1(131,1) v1(133,99) v1(133,5) v1(133,3) v1(133,1) v1(133.25,70.62) v1(133.25,70) v1(133.75,68.62) v1(133.75,68) v1(135,99) v1(135,9) v1(135,7) v1(135,5) v1(135,3) v1(135,1) v1(135.62,76.5) v1(136.38,76.5) v1(137,99) v1(137,9) v1(137,7) v1(137,5) v1(137,3) v1(137,1) v1(137.12,76.5) v1(139,99) v1(139,9) v1(139,7) v1(139,5) v1(139,3) v1(139,1) v1(139.38,67.5) v1(139.62,69.12) v1(140.88,70.25) v1(141,99) v1(141,9) v1(141,7) v1(141,5) v1(141,3) v1(141,1) v1(141.25,60.5) v1(141.38,57.88) v1(142.5,71.25) v1(143,99) v1(143,86.12) v1(143,85.25) v1(143,84.38) v1(143,17) v1(143,15) v1(143,13) v1(143,11) v1(143,9) v1(143,7) v1(143,5) v1(143,3) v1(143,1) v1(143.25,71.25) v1(143.5,89.12) v1(143.5,88.5) v1(143.5,87.88) v1(143.5,85.75) v1(143.5,84.88) v1(143.5,82.62) v1(143.5,81.88) v1(143.5,81.12) v1(143.75,61.25) v1(143.88,84.38) v1(144,86.12) v1(144,85.25) v1(144.5,60.38) v1(144.5,57.88) v1(145,99) v1(145,17) v1(145,15) v1(145,13) v1(145,11) v1(145,9) v1(145,7) v1(145,5) v1(145,3) v1(145,1) v1(146.38,58) v1(147,99) v1(147,17) v1(147,15) v1(147,13) v1(147,11) v1(147,9) v1(147,7) v1(147,5) v1(147,3) v1(147,1) v1(147.75,38) v1(148,90.5) v1(148.5,89.6) v1(149,99) v1(149,17) v1(149,15) v1(149,13) v1(149,11) v1(149,9) v1(149,7) v1(149,5) v1(149,3) v1(149,1) v1(149.25,90.5) v1(149.75,58.25) v1(150.62,58.25) v1(151,99) v1(151,17) v1(151,15) v1(151,13) v1(151,11) v1(151,9) v1(151,7) v1(151,5) v1(151,3) v1(151,1) v1(151.75,38) v1(152.75,84.5) v1(153,99) v1(153,29) v1(153,17) v1(153,15) v1(153,13) v1(153,11) v1(153,9) v1(153,7) v1(153,5) v1(153,3) v1(153,1) v1(153.5,24.25) v1(153.75,33.5) v1(154.25,42.25) v1(155,99) v1(155,17) v1(155,15) v1(155,13) v1(155,11) v1(155,9) v1(155,7) v1(155,5) v1(155,3) v1(155,1) v1(155.5,38) v1(155.88,51) v1(156.5,24.5) v1(156.75,51) v1(157,99) v1(157,17) v1(157,15) v1(157,13) v1(157,11) v1(157,9) v1(157,7) v1(157,5) v1(157,3) v1(157,1) v1(157.5,29.25) v1(157.62,51) v1(158.25,33.75) v1(158.75,42.25) v1(159,99) v1(159,63) v1(159,61) v1(159,59) v1(159,57) v1(159,55) v1(159,53) v1(159,17) v1(159,15) v1(159,13) v1(159,11) v1(159,9) v1(159,7) v1(159,5) v1(159,3) v1(159,1) v1(160,38) v1(160.5,49.5) v1(161,99) v1(161,63) v1(161,61) v1(161,59) v1(161,57) v1(161,55) v1(161,53) v1(161,17) v1(161,15) v1(161,13) v1(161,11) v1(161,9) v1(161,7) v1(161,5) v1(161,3) v1(161,1) v1(161.5,49.5) v1(163,99) v1(163,63) v1(163,61) v1(163,59) v1(163,57) v1(163,55) v1(163,53) v1(163,17) v1(163,15) v1(163,13) v1(163,11) v1(163,9) v1(163,7) v1(163,5) v1(163,3) v1(163,1) v1(164.88,87.75) v1(164.88,87.12) v1(164.88,86.38) v1(164.88,83.88) v1(164.88,83.12) v1(164.88,82.38) v1(165,99) v1(165,63) v1(165,61) v1(165,59) v1(165,57) v1(165,55) v1(165,53) v1(165,17) v1(165,15) v1(165,13) v1(165,11) v1(165,9) v1(165,7) v1(165,5) v1(165,3) v1(165,1) v1(166,48.12) v1(166,46.25) v1(166,44.38) v1(167,99) v1(167,79) v1(167,77) v1(167,75) v1(167,73) v1(167,71) v1(167,69) v1(167,67) v1(167,65) v1(167,63) v1(167,61) v1(167,59) v1(167,57) v1(167,55) v1(167,53) v1(167,1) v1(168.88,85.25) v1(169,99) v1(169,79) v1(169,77) v1(169,75) v1(169,73) v1(169,71) v1(169,69) v1(169,67) v1(169,65) v1(169,63) v1(169,61) v1(169,59) v1(169,57) v1(169,55) v1(169,53) v1(169,1) v1(169.75,85.25) v1(170.62,85.25) v1(170.62,10.38) v1(170.62,9.38) v1(170.75,12.62) v1(170.75,11.62) v1(171,99) v1(171,79) v1(171,77) v1(171,75) v1(171,73) v1(171,71) v1(171,69) v1(171,67) v1(171,65) v1(171,63) v1(171,61) v1(171,59) v1(171,57) v1(171,1) v1(173,99) v1(173,79) v1(173,77) v1(173,75) v1(173,73) v1(173,71) v1(173,69) v1(173,67) v1(173,65) v1(173,63) v1(173,61) v1(173,59) v1(173,57) v1(173,1) v1(174,91.5) v1(174,90.5) v1(174.5,13.5) v1(175,99) v1(175,1) v1(176.25,90.5) v1(177,99) v1(177,1) v1(179,99) v1(179,1) v1(179.62,89.25) v1(180.38,89.25) v1(181,99) v1(181,1) v1(181.75,88) v1(182.62,88) v1(183,99) v1(183,1) v1(183.5,88) v1(185,99) v1(185,1) v1(187,99) v1(187,1) v1(189,99) v1(189,1) v1(191,99) v1(191,97) v1(191,95) v1(191,93) v1(191,91) v1(191,89) v1(191,87) v1(191,85) v1(191,83) v1(191,81) v1(191,79) v1(191,77) v1(191,75) v1(191,73) v1(191,71) v1(191,69) v1(191,67) v1(191,65) v1(191,63) v1(191,61) v1(191,59) v1(193,99) v1(193,97) v1(193,95) v1(193,93) v1(193,91) v1(193,89) v1(193,87) v1(193,85) v1(193,83) v1(193,81) v1(193,79) v1(193,77) v1(193,75) v1(193,73) v1(193,71) v1(193,69) v1(193,67) v1(193,65) v1(193,63) v1(193,61) v1(193,59) v1(195,99) v1(195,97) v1(195,95) v1(195,93) v1(195,91) v1(195,89) v1(195,87) v1(195,85) v1(195,83) v1(195,81) v1(195,79) v1(195,77) v1(195,75) v1(195,73) v1(195,71) v1(195,69) v1(195,67) v1(195,65) v1(195,63) v1(195,61) v1(195,59) v1(197,99) v1(197,97) v1(197,95) v1(197,93) v1(197,91) v1(197,89) v1(197,87) v1(197,85) v1(197,83) v1(197,81) v1(197,79) v1(197,77) v1(197,75) v1(197,73) v1(197,71) v1(197,69) v1(197,67) v1(197,65) v1(197,63) v1(197,61) v1(197,59) v1(199,99) v1(199,97) v1(199,95) v1(199,93) v1(199,91) v1(199,89) v1(199,87) v1(199,85) v1(199,83) v1(199,81) v1(199,79) v1(199,77) v1(199,75) v1(199,73) v1(199,71) v1(199,69) v1(199,67) v1(199,65) v1(199,63) v1(199,61) v1(199,59) v1(199,57) v1(199,55) v1(199,53) v1(199,51) v1(199,49) v1(199,47) v1(199,45) v1(199,43) v1(199,41) v1(199,39) v1(199,37) v1(199,35) v1(199,33) v1(199,31) v1(199,29) v1(199,27) v1(199,25) v1(199,23) v1(199,21.25) v1(199,19) v1(199,17) v1(199,15) v1(199,13) v1(199,11) v1(199,9) v1(199,7) v1(199,5) v1(199,3) v1(199,1) v3(9.5,61.75) v3(9.5,59.75) v3(9.5,57.75) v3(9.5,42.25) v3(9.5,40.25) v3(9.5,38.25) v3(11.4,60.75) v3(11.4,59.75) v3(11.4,58.75) v3(11.4,57.75) v3(11.4,42.25) v3(11.4,41.25) v3(11.4,40.25) v3(11.4,39.25) v3(13.6,60.75) v3(13.6,59.75) v3(13.6,58.75) v3(13.6,57.75) v3(13.6,42.25) v3(13.6,41.25) v3(13.6,40.25) v3(13.6,39.25) v3(15.5,61.75) v3(15.5,59.75) v3(15.5,57.75) v3(15.5,42.25) v3(15.5,40.25) v3(36.75,64.5) v3(36.75,62.5) v3(36.75,60.5) v3(36.75,39.5) v3(36.75,37.5) v3(36.75,35.5) v3(38.65,63.5) v3(38.65,62.5) v3(38.65,61.5) v3(38.65,60.5) v3(38.65,39.5) v3(38.65,38.5) v3(38.65,37.5) v3(38.65,36.5) v3(40.85,63.5) v3(40.85,62.5) v3(40.85,61.5) v3(40.85,60.5) v3(40.85,39.5) v3(40.85,38.5) v3(40.85,37.5) v3(40.85,36.5) v3(42.75,64.5) v3(42.75,62.5) v3(42.75,60.5) v3(42.75,39.5) v3(42.75,37.5) v3(42.75,35.5) v4(11,62.25) v4(11,37.75) v4(14,62.25) v4(14,37.75) v4(38.25,65) v4(38.25,35) v4(41.25,65) v4(41.25,35)
A: length 22.9
  TOP w0.5: U9.8 98.01,24.31 98.07,24.25 98.5,24.25 99,23.75 99,22.75 99.98,21.77 U9.5 108.48,21.77 A.1
B: length 13.5
  TOP w0.25: U9.6 113.55,23.04 113.59,23 B.1
CONVST: length 4.6
  TOP w0.25: R23.1 173.25,24.5 173,24.25 173,22.75 173.5,22.25 R24.1
CONVSTB: length 81.5
  TOP w0.25: U2.6 106.5,49.25 115.25,40.5 T6.1 139.75,26.75 R25.2
CSB: length 84
  TOP w0.25: R19.2 172.75,29 172.25,29.5 172.25,31.25 ; 172.25,31.25 140,31.25 T7.1 111.14,45.25 106.64,49.75 U2.7 ; 172.25,31.25 R21.2
GPIO1: length 88.1
  TOP w0.25: J4.78 187.5,21 187,20.5 168.25,20.5 167.5,19.75 140.5,19.75 128.5,7.75 GPIO1.1 D2.C
GPIO2: length 97.8
  TOP w0.25: v1(169.25,22) 130.5,22 122,30.5 GPIO2.1 113.59,30.5 113.34,30.75 D3.C ; J4.44 v1(198.65,20.4) ; v1(188.75,19.75) v1(169.25,19.75)
  BOTTOM w0.25: v1(188.75,19.75) 189.4,20.4 v1(198.65,20.4) ; v1(169.25,19.75) v1(169.25,22)
RF1: length 11.2
  TOP w0.356: 39.75,51.25 U10.7 39.75,52.14 RF1.1
RF2: length 11.3
  TOP w0.356: RF2.1 39.75,47.86 U10.14 39.75,48.81
RF_TRUE_CAL: length 19.5
  TOP w0.356: J5.1 J3.1
RFIN: length 10.5
  TOP w0.356: 41.19,50.25 U10.3 42.14,50.25 U1.5
SCLK: length 82.2
  TOP w0.25: R17.2 172.75,33.5 172.5,33.75 172.5,35.75 ; 172.5,35.75 140.25,35.75 T8.1 107.03,50 106.78,50.25 U2.8 ; 172.5,35.75 R20.2
SDO: length 84
  TOP w0.25: R22.2 172.5,38 172.49,38.01 172.49,40.25 ; 172.49,40.25 R18.2 ; 172.49,40.25 140.5,40.25 T9.1 116.5,54.75 112.5,50.75 U2.9
UNNAMED_3_AD7091RV2_I14_REFOUT: length 17.3
  TOP w0.25: C11.1 96.15,50.75 U2.2
  TOP w0.5: T2.1 88.25,55.09 91.55,51.8 C12.1 93.15,51.65 C11.1
UNNAMED_3_AD7091RV2_I14_VIN: length 18.2
  TOP w0.25: U2.3 91.5,50.25 91.25,50.5 90.36,50.5 C37.1
  TOP w0.5: C37.1 89.39,50.38 89.36,50.35 R40.1 85.38,50.35 85.28,50.25 T3.1 R31.2
UNNAMED_3_CAP_I29_N1: length 9.9
  TOP w0.25: 95,47 95,48.75 96,49.75 U2.4
  TOP w0.5: T4.1 93,45 95,47 C14.1
UNNAMED_4_ADM660_I4_CAP: length 2.8
  TOP w0.5: C36.N 141.4,56.59 U11.4
UNNAMED_4_ADM660_I4_CAP_1: length 2.7
  TOP w0.5: C36.P 141.13,59.13 U11.2
UNNAMED_4_ADM7170_I67_VOUT1: length 0.5
  TOP w0.25: U8.2 U8.1
UNNAMED_4_ADP2301_I57_EN: length 14.7
  TOP w0.5: U7.4 v1(172.69,92.44) ; R14.1 162,87.3 v1(162,88.75)
  BOTTOM w0.5: v1(172.69,92.44) 165.69,92.44 v1(162,88.75)
UNNAMED_4_ADP3303_I47_ERRN: length 12.6
  TOP w0.5: v1(137.75,70) 138.63,70 R12.1 ; U6.6 v1(129.63,74.39)
  BOTTOM w0.5: v1(129.63,74.39) 133.37,74.39 v1(137.75,70)
UNNAMED_5_CN120PV4_I55_EEPROMA0: length 27.2
  TOP w0.25: R28.1 174.48,9.75 174.53,9.7 U5.1 176.02,8.71 176,8.69 176,8.25 176.5,7.75 190.12,7.75 195.58,13.2 J4.56
UNNAMED_5_CN120PV4_I55_GPIO0: length 24.8
  TOP w0.25: v1(188,22.75) 187.57,22.75 187.24,23.08 183.05,23.08 182.21,22.25 177.75,22.25 R24.2 ; J4.43 v1(198.25,21)
  BOTTOM w0.25: v1(188,22.75) 189.75,21 v1(198.25,21)
UNNAMED_5_CN120PV4_I55_SCL0: length 17.9
  TOP w0.25: J4.79 v1(185.85,21.6) ; U5.6 177.33,15.29 177.25,15.36 v1(177.25,16)
  BOTTOM w0.25: v1(177.25,16) 182.85,21.6 v1(185.85,21.6)
UNNAMED_5_CN120PV4_I55_SDA0: length 18.4
  TOP w0.25: v1(187,22.5) 187.3,22.2 187.73,22.2 187.76,22.17 188.24,22.17 188.27,22.2 J4.80 ; U5.5 178,14.32 v1(178,15.75)
  BOTTOM w0.25: v1(178,15.75) 182.75,20.5 186.5,20.5 187,21 v1(187,22.5)
UNNAMED_5_CN120PV4_I55_SPICLK: length 22.8
  TOP w0.25: v1(177.75,33.5) R17.1 ; J4.82 187.56,23.4 187.43,23.54 182.86,23.54 182.74,23.42 181.83,23.42 181.25,24 181.25,24.25 v1(179.75,25.75)
  BOTTOM w0.25: v1(177.75,33.5) 179.75,31.5 v1(179.75,25.75)
UNNAMED_5_CN120PV4_I55_SPIMISO: length 30.9
  TOP w0.25: J4.83 v1(182.5,24) ; v1(181.75,40.25) R18.1
  BOTTOM w0.25: v1(182.5,24) 182.5,39.5 v1(181.75,40.25)
UNNAMED_5_CN120PV4_I55_SPISELA: length 16.6
  TOP w0.25: R19.1 178,29 181.8,25.2 J4.85
UNNAMED_5_CN120PV4_I55_SPORTDR0: length 20.9
  TOP w0.25: J4.91 184.45,28.8 v1(178.75,34.5) ; v1(178.75,38) R22.1
  BOTTOM w0.25: v1(178.75,34.5) v1(178.75,38)
UNNAMED_5_CN120PV4_I55_SPORTRFS: length 18.6
  TOP w0.25: 189.5,28.2 181.3,28.2 178.25,31.25 R21.1 ; 189.5,28.2 J4.90 ; 189.5,28.2 189.5,27.6 J4.89
UNNAMED_5_CN120PV4_I55_SPORTRSC: length 24.5
  TOP w0.25: J4.87 v1(187.65,26.4) ; R20.1 179.25,35.75 185.25,29.75 v1(187.65,29.75) 188.88,29.75 189.23,29.4 J4.92
  BOTTOM w0.25: v1(187.65,26.4) v1(187.65,29.75)
UNNAMED_5_CN120PV4_I55_TMRA: length 30.5
  TOP w0.25: J4.48 v1(198.25,18) ; v1(177.5,18.25) 178.5,17.25 v1(188.25,17.25) ; v1(177.5,24.5) R23.2
  BOTTOM w0.25: v1(198.25,18) 189,18 v1(188.25,17.25) ; v1(177.5,18.25) v1(177.5,24.5)
UNNAMED_5_CN120PV4_I55_TMRB: length 22.7
  TOP w0.25: J4.73 179.5,18 v1(178.5,19) ; 178.55,25.7 v1(178.5,25.75) 177.5,26.75 R25.1
  BOTTOM w0.25: v1(178.5,19) v1(178.5,25.75)
UNNAMED_5_IC24FC256_I33_A1: length 9.1
  TOP w0.25: R26.2 171.9,14.1 172.5,13.5 173.25,13.5 173.5,13.25 173.5,13.03 173.6,12.93 R27.1 175.5,12 176.67,10.83 U5.2
UNNAMED_8_7404_I38_IN: length 64.2
  TOP w0.25: R41.1 v1(46.5,44.5)
  TOP w0.5: U9.11 v1(94.75,20.5) 94.25,20 94.25,19.73 94.75,19.23 U9.12
  BOTTOM w0.25: v1(94.75,20.5) 70.75,44.5 v1(46.5,44.5)
UNNAMED_8_7404_I38_OUTN: length 68.5
  TOP w0.25: R42.1 v1(46.5,56) ; U9.10 96.44,21.75 v1(95,21.75)
  BOTTOM w0.25: v1(95,21.75) 71,45.75 57.75,45.75 56.75,46.75 56.75,52.75 53.5,56 v1(46.5,56)
UNNAMED_8_7404_I39_IN: length 15.5
  TOP w0.5: U9.13 94.71,17.96 94,17.25 94,14.25 96,12.25 R30.1 98.4,9.21 98.34,9.16 D2.A
UNNAMED_8_7404_I65_IN: length 13.4
  TOP w0.5: U9.9 94.79,23.04 93.75,24.08 93.75,25 95.75,27 R36.1 98.4,29.15 98.59,29.34 D3.A
UNNAMED_8_ADL6010_I98_VOUT: length 5.7
  TOP w0.3: C3.1 54.74,50.13 54.63,50.25 U1.2
  TOP w0.5: R1.1 58.47,50.25 58.35,50.13 C3.1
UNNAMED_8_ICHMC547LP3E_I42_A: length 16
  TOP w0.25: v1(43.5,44.5) R41.2 ; U10.11 38.07,49.75 v1(37.82,49.5)
  BOTTOM w0.25: v1(43.5,44.5) 41.75,44.5 41.5,44.25 36.5,44.25 36,44.75 36,49.25 36.33,49.58 37.74,49.58 v1(37.82,49.5)
UNNAMED_8_ICHMC547LP3E_I42_B: length 15.9
  TOP w0.25: U10.10 v1(37.75,50.25) ; v1(43.5,56) R42.2
  BOTTOM w0.25: v1(37.75,50.25) 36.5,50.25 36,50.75 36,55.25 36.5,55.75 41.5,55.75 41.75,56 v1(43.5,56)
V_IN: length 0.5
  TOP w0.25: U8.7 U8.8
V_OUT: length 17.5
  TOP w0.5: R31.1 V_OUT.1 R1.2
VDET: length 1.2
  TOP w0.5: v2(153,79) v2(153,77.75)
  vias: v2(149,65.75) v2(149,64.75) v2(150.25,65.75) v2(150.25,64.75) v2(151.5,65.75) v2(151.5,64.75) v2(154,79) v2(154,77.75) v2(155,79) v2(155,77.75)
VIO_CONNECTOR: length 40.7
  TOP w0.3: U5.3 177.33,11.67 176,13 176,14.28 U5.8 175.8,14.3
  TOP w0.8: 175.8,14.3 175.7,14.3 174.75,15.25 R26.1
  TOP w1: R26.1 v1(173.6,17.15)
  BOTTOM w1: v1(173.6,17.15) 173.6,42.15 v1(169.5,46.25)
VNEG:
  vias: v2(118.75,27) v2(118.75,25.75) v2(118.75,24.25) v2(120.25,27) v2(120.25,25.75) v2(120.25,24.25)

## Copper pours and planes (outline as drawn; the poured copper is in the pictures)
AGND on TOP (solid shape): 9.38,57.88 9.25,57.75 6.12,57.75 6,57.88 6,61.25 9.38,61.25
AGND on TOP (solid shape): 9.5,38.88 9.38,38.75 6.25,38.75 6.12,38.88 6.12,42.25 9.5,42.25
AGND on TOP (solid shape): 18.88,57.88 18.75,57.75 15.62,57.75 15.5,57.88 15.5,61.25 18.88,61.25
AGND on TOP (solid shape): 18.88,39 18.75,38.88 15.62,38.88 15.5,39 15.5,42.38 18.88,42.38
AGND on TOP (solid shape): 36.62,60.62 36.5,60.5 33.38,60.5 33.25,60.62 33.25,64 36.62,64
AGND on TOP (solid shape): 36.75,36.12 36.62,36 33.5,36 33.38,36.12 33.38,39.5 36.75,39.5
